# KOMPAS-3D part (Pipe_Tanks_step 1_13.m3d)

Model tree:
1. X Axis
2. Y Axis
3. Z Axis  (labels: Bend 90 Dn 50; Pipe Dn 50; C:\Program Files\ASCON\KOMPAS-3D V10\Sys\graphic.lyt; Pipe_Tanks_step 1_13.m3d)
     Òîëùèíà ñòåíêè 1 = 1

Referenced files in C:\Documents and Settings\kashirsky\Мои документы\Camtasia Studio\Pipelines3D\Tanks\: Tanks_step 1.a3d, Tanks_step 1.spw
Referenced files in C:\Documents and Settings\kashirsky\Мои документы\Camtasia Studio\Pipelines3D\Tanks\Tanks_step 1_Pipes\: Pipe_Tanks_step 1_13.m3d
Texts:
  Pipe Dn 50
  Steel ASTM A295
  Three Point Plane
  Plane at Angle
  Line and Point Plane
  Axis through Two Vertices
  Axis of Feature
  Axis of Conical Surface
  Axis through Edge
  Trim by Surface
  Trim by Sketch
  Feature with No History
  Intersection Axis of Two Planes
  Two Line Plane
  Line and Face Plane
  Bend by line
  Hole in sheet body
  Cut in sheet body
  Point in CM
  Linear Dimension from Line to Point
  Surface Finish Symbol
  Geometric Tolerance Symbol
  Leader #1
  Leader #2
  Leader #3
  Shape Deviations and Datum
  Node point number
  Mark of coordination axis
  Node point designation
  Mark/Reference designation with leader
  Mark/reference designation on line
  Mark/Reference designation without leader
  Bend 90 Dn 50
  Plane of section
